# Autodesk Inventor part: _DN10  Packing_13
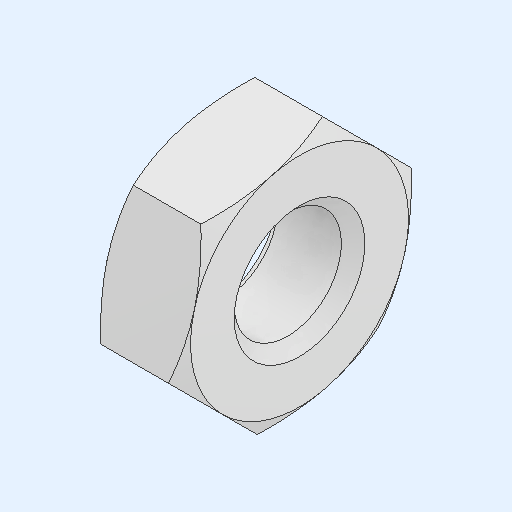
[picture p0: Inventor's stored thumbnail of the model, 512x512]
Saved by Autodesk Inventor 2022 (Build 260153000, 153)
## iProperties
Created: 2021-12
Part Number: _DN10  Packing_13
Material: Generico
Document SubType Name: Modeling
Designer: admin
Density: 1 g/cm^3
Appearance: Default
Author: admin
Revision Number: NONE
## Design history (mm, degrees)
feature "_DN10  Packing"
node "Solido1"
